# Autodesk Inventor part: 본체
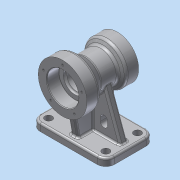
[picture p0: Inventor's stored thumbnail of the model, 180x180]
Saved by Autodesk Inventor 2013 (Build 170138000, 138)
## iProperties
Created: 2015-08
Part Number: 본체
Material: 알루미늄 6061
Document SubType Name: Modeling
Designer: Administrator
Density: 2.71 g/cm^3
Mass: 1062.91 g
Surface Area: 749.651 cm^2
Volume: 392.217 cm^3
Author: Administrator
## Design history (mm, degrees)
sketch "스케치2"
  geometry: L1 (-61, 40)-(61, 40); L2 (61, 40)-(61, -40); L3 (61, -40)-(-61, -40); L4 (-61, -40)-(-61, 40); L5 (-61, 40)-(61, -40); L6 (61, 40)-(-61, -40); 1 further point
  constraints: 12 end point, 2 midpoint, 2 parallel, 1 horizontal, 1 perpendicular
  dimensions: "d0" = 122 distance of L2.end L3.end; "d1" = 80 distance of L1.end L2.end
extrude "돌출1" new body sketch "스케치2" distance "d2" = 12; taper "d3" = 0 deg
sketch "스케치4"
  geometry: L1 (90, 50)-(90, -40); L2 (0, -40)-(0, 40) reference; L3 (90, 50)-(130, 50); L4 (130, 50)-(130, 30); L5 (130, 30)-(116, 13.315); L6 (116, 13.315)-(116, -14.804); L7 (116, -14.804)-(125, -20); L8 (125, -20)-(125, -40); L9 (125, -40)-(90, -40); L10 (0, 40)-(12, 40) reference; L11 (0, -40)-(12, -40) reference; 2 further points
  constraints: 16 end point, 3 parallel, 2 perpendicular, 1 midpoint, 1 vertical
  dimensions: "d29" = 90 distance between parallel lines of L2 L1; "d30" = 80 diameter of L4 L1; "d31" = 52 diameter of L6 L1; "d32" = 70 diameter of L8 L1; "d33" = 20 distance of L3.end L4.end; "d34" = 20 distance of L7.end L8.end; "d35" = 40 deg angle of L6 L5; "d36" = 60 deg angle of L6 L7; "d37" = 90 distance between parallel lines of L9 L3; "d123" = 0 distance between parallel lines of L9 L11
revolve "회전1" sketch "스케치4" stored, may be unused: angle "d38" = 90 deg
sketch "스케치5"
  geometry: C1 r 40 at (0, 0) reference; C2 r 26 at (0, 0); 1 further point
  constraints: 1 centre point, 1 coincident
  dimensions: "d39" = 52 diameter of C2
extrude "돌출2" cut sketch "스케치5" distance "d40" = 20; taper "d41" = 0 deg
sketch "스케치6"
  geometry: C1 r 26 at (0, 0) reference; C2 r 19 at (0, 0); 1 further point
  constraints: 1 centre point, 1 coincident
  dimensions: "d42" = 38 diameter of C2
extrude "돌출3" cut sketch "스케치6" distance "d43" = 3; taper "d44" = 0 deg
sketch "스케치7"
  geometry: C1 r 19 at (0, 0) reference; C2 r 16 at (0, 0); 1 further point
  constraints: 1 centre point, 1 coincident
  dimensions: "d45" = 32 diameter of C2
extrude "돌출4" cut sketch "스케치7" stored distance "d46" = 3; taper "d47" = 0 deg
sketch "스케치8"
  geometry: C1 r 16 at (0, 0) reference; C2 r 35 at (0, 0) reference; C3 r 20 at (0, 0); 1 further point
  constraints: 1 centre point, 1 coincident
  dimensions: "d48" = 40 diameter of C3
extrude "돌출5" cut sketch "스케치8" distance "d49" = 17; taper "d50" = 0 deg
sketch "스케치9"
  geometry: L1 (64, -14.804)-(116, -14.804) reference; L2 (64, 13.315)-(116, 13.315) reference; L3 (7.99, -30)-(62.455, -30); L4 (0, -40)-(12, -40) reference; L5 (0, 40)-(12, 40) reference; L6 (62.543, 38.912)-(12, 30); L7 (12, -40)-(12, 40) reference; L8 (12, 30)-(4.609, 30); L9 (4.609, 30)-(4.609, -30); L10 (4.609, -30)-(7.99, -30); L11 (62.543, 38.912)-(62.543, 30.118); L12 (62.543, 30.118)-(71.523, 23.298); L13 (71.523, 23.298)-(71.523, -18.06); L14 (71.523, -18.06)-(62.455, -30)
  constraints: 18 end point, 5 perpendicular, 2 parallel
  dimensions: "d124" = 10 distance between parallel lines of L4 L3; "d126" = 10 distance from line of L6.end L5; "d127" = 80 deg angle of L6 L7
extrude "돌출6" join sketch "스케치9" stored distance "d56" = 12; taper "d57" = 0 deg
sketch "스케치10"
  geometry: L1 (61, 12)-(61, 0) reference; L2 (61, 0)-(-61, 0) reference; L3 (-61, 0)-(-61, 12) reference; L4 (-61, 12)-(-6, 12) reference; L5 (-6, 12)-(-6, 64.702) reference; L6 (6, 64.702)-(6, 12) reference; L7 (6, 12)-(61, 12) reference; L8 (-51, 12)-(-25.091, 83.185); L9 (-6, 64.702)-(-6, 12); L10 (-51, 12)-(-6, 12); L11 (51, 12)-(25.091, 83.185); L12 (6, 64.702)-(6, 12); L13 (51, 12)-(6, 12); C1 r 16 at (0, 90) reference; A1 r 26 centre (0, 90) between (6, 64.702) and (-6, 64.702) reference; A2 r 26 centre (0, 90) between (-25.091, 83.185) and (-6, 64.702); A3 r 26 centre (0, 90) between (6, 64.702) and (25.091, 83.185); 1 further point
  constraints: 13 end point, 4 point on circle, 2 centre point, 2 collinear, 2 point on line, 1 coincident
  dimensions: "d58" = 10 distance from line of L8.start L3; "d59" = 70 deg angle of L4 L8
extrude "돌출7" join sketch "스케치10" stored distance "d60" = 12; taper "d61" = 0 deg
sketch "스케치11"
  geometry: C1 r 6 at (-47, 26); C2 r 6 at (47, 26); C3 r 6 at (-47, -26); C4 r 6 at (47, -26); 1 further point
  constraints: 4 centre point
  dimensions: "d62" = 12 diameter of C1; "d63" = 12 diameter of C2; "d64" = 12 diameter of C3; "d65" = 12 diameter of C4; "d66" = 94 distance of C2.centre C1.centre; "d67" = 94 distance of C4.centre C3.centre; "d68" = 52 distance of C3.centre C1.centre; "d69" = 26 vertical distance of point (0, 0) C1.centre; "d70" = 47 horizontal distance of point (0, 0) C1.centre; "d71" = 52 distance of C4.centre C2.centre; "d72" = 26 vertical distance of point (0, 0) C2.centre; "d73" = 47 horizontal distance of point (0, 0) C3.centre
extrude "돌출8" cut sketch "스케치11" stored distance "d74" = 12; taper "d75" = 0 deg
sketch "스케치12"
  geometry: 2 further points
hole "구멍1" sketch "스케치12" at (0, 33) diameter "d77" = 3.242; stored, may be unused: countersink angle "d81" = 90 deg, drill point angle "d83" = 118 deg; dims "d78" = 10, "d79" = 4, "d80" = 2, "d82" = 13
sketch "스케치13"
  geometry: 2 further points
hole "구멍2" sketch "스케치13" at (0, 27) diameter "d88" = 3.242; stored, may be unused: countersink angle "d92" = 90 deg, drill point angle "d94" = 118 deg; dims "d89" = 10, "d90" = 4, "d91" = 2, "d93" = 13
fillet "모깎기2" dims "d99" = 0.3
fillet "모깎기3" dims "d100" = 14
sketch "스케치14"
  geometry: L1 (51, 12)-(6, 12) reference; L2 (51, 12)-(25.091, 83.185) reference; L3 (6, 12)-(6, 64.702) reference; L4 (47, 0)-(-47, 0) reference; L5 (-24, 42)-(-24, 42); L6 (-18, 36)-(-18, 30); L7 (-24, 24)-(-24, 24); L8 (-30, 30)-(-30, 36); L9 (24, 42)-(24, 42); L10 (30, 36)-(30, 30); L11 (24, 24)-(24, 24); L12 (18, 30)-(18, 36); A1 r 26 centre (0, 90) between (6, 64.702) and (25.091, 83.185) reference; A2 r 6 centre (-24, 36) between (-24, 42) and (-30, 36); A3 r 6 centre (-24, 36) between (-18, 36) and (-24, 42); A4 r 6 centre (-24, 30) between (-30, 30) and (-24, 24); A5 r 6 centre (-24, 30) between (-24, 24) and (-18, 30); A6 r 6 centre (24, 36) between (24, 42) and (18, 36); A7 r 6 centre (24, 36) between (30, 36) and (24, 42); A8 r 6 centre (24, 30) between (24, 24) and (30, 30); A9 r 6 centre (24, 30) between (18, 30) and (24, 24); 7 further points
  constraints: 16 end point, 16 point on circle, 16 tangent, 12 point on line, 8 centre point, 7 equal radius, 4 parallel, 2 horizontal, 2 perpendicular
  dimensions: "d105" = 12 distance of point (-30, 42) point (-18, 42); "d106" = 18 distance of point (-30, 24) point (-30, 42); "d107" = 12 distance of point (18, 42) point (30, 42); "d108" = 18 distance of point (30, 42) point (30, 24); "d111" = 60 distance between parallel lines of L10 L8; "d112" = 30 distance from line of point (0, 0) L8; "d113" = 6 radius of A2
extrude "돌출9" cut sketch "스케치14" stored distance "d114" = 12; taper "d115" = 0 deg
fillet "모깎기5" dims "d117" = 3
chamfer "모따기1" distance "d119" = 1; stored, may be unused: second distance "d120" = 2, angle "d121" = 45 deg
fillet "모깎기7" dims "d122" = 3
fillet "모깎기9" dims "d129" = 3
fillet "모깎기10" dims "d130" = 3
fillet "모깎기12" dims "d132" = 5
fillet "모깎기13" dims "d133" = 3
fillet "모깎기14" dims "d134" = 3
fillet "모깎기15" dims "d135" = 3
fillet "모깎기16" dims "d136" = 3
sketch "스케치15"
  geometry: L1 (-37, 12)-(-26, 12) reference; L2 (-30, 52.119)-(-30, 15) reference; 2 further points
  constraints: 1 other
  dimensions: "d137" = 24 distance from line of L1 point (-14, 36); "d138" = 16 distance from line of point (-14, 36) L2
feature "엠보싱1" sketch "스케치15" dims "d0" = 122, "d1" = 80, "d139" = 0.5, "d140" = 0
node "솔리드1"
pattern_circular "원형 패턴1" dims angle "d85" = 360 deg
pattern_circular "원형 패턴2" dims angle "d96" = 360 deg
node "투영된 루프1"
node "투영된 루프2"
node "절단 모서리 투영1"
